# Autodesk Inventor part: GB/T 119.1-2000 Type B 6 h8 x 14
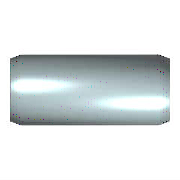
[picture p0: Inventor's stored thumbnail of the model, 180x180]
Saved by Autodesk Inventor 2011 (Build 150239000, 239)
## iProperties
Created: 2010-02
Part Number: GB/T 119.1-2000 Type B 6 h8 x 14
Material: 低炭钢
Description: B 型圆柱销
Document SubType Name: Modeling
Standard: GB/T 119.1-2000
Designer: Administrator
Standard Revision: 2000
Standards Organization: GB
Language: zh-CN
Size Designation: B 6 x 14
Categories: <MemberInstance><Categories><Category DisplayName="紧固件" InternalName="e4da775c-781d-43d5-af7c-5136215cf5a6" Mnemonic="FSTN"><Category DisplayName="销" InternalNa
Density: 1 g/cm^3
IsCustomPart: 1
Author: Administrator
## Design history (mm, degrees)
sketch "Sketch"
  geometry: C1 r 3 at (0, 0); 1 further point
  constraints: 1 centre point, 1 coincident
  dimensions: "d1" = 6 diameter of C1 (= NND)
extrude "Body" new body sketch "Sketch" distance "d2" = 14 (= NLG); taper "d3" = 0 deg
chamfer "Chamfer1" distance "d4" = 1.2 (= PHH); stored, may be unused: angle "d5" = 15 deg (= FAWI), second distance "d11" = 1.2 (= PHH)
chamfer "Chamfer2" distance "d8" = 1.2 (= PHH); stored, may be unused: angle "d9" = 15 deg (= FAWI), second distance "d12" = 1.2 (= PHH)
body "Solid1"
other parameters: "NND" = 6 [user parameter; used in 1 equation term], "NLG" = 14 [user parameter; used in 1 equation term], "PHH" = 1.2 [user parameter; used in 4 equation terms], "FAWI" = 15 deg [user parameter; used in 2 equation terms], "d13" = 0, "d15" = 0, "d16" = 0, "KAH" = 0 [user parameter]
